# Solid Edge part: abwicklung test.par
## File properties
Author: Administrator
Template: Sheet Metal2
Last saved by: Administrator
Revision: 2
Application: Solid Edge
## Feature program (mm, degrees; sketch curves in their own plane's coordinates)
body "unnamed Body 1"
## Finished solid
Body 1: solid body, 48 faces, 98 edges, 52 vertices.
  Faces by surface: plane 48
  Edges by curve: line 82, curve on surface 16
Bounding box of the edges (mm): 158.788 x 185.993 x 2.000, from (-79.3942, -106.5991, 0) to (79.3942, 79.3942, 2).
Planar faces by outward normal: +x 2, +y 1, +z 11, -x 2, -y 1, -z 11, oblique 20
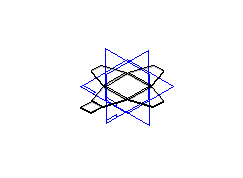
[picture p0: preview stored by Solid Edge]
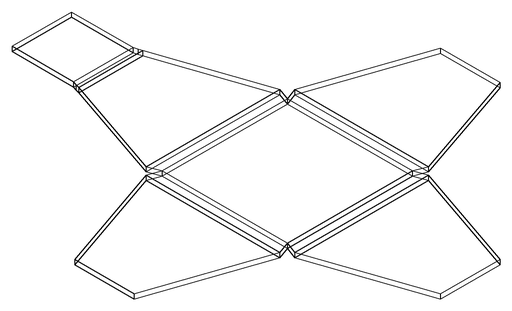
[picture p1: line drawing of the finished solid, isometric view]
